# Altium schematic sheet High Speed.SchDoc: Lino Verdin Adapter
size A3; Organization: Toradex AG; Address1: Ebenaustrasse 10; Address2: Horw; Address3: 6048; Address4: Switzerland; DocumentNumber: 5; Revision: V1.1; SheetNumber: 5; SheetTotal: 8; PageSetup: Record=PageOptions¦CenterHorizontal=True¦CenterVertical=True¦PrintScale=0.73¦XCorrection=1.00¦YCorrection=1.00¦PrintKind=0¦BorderSize=5000000¦LeftOffset=0¦BottomOffset=0¦Orientation=2¦PaperLength=1000¦PaperWidth=1000¦Scale=100¦PaperSource=7¦PrintQuality=-4¦MediaType=1¦DitherType=10¦PaperKind=A4¦PrintScaleMode=1
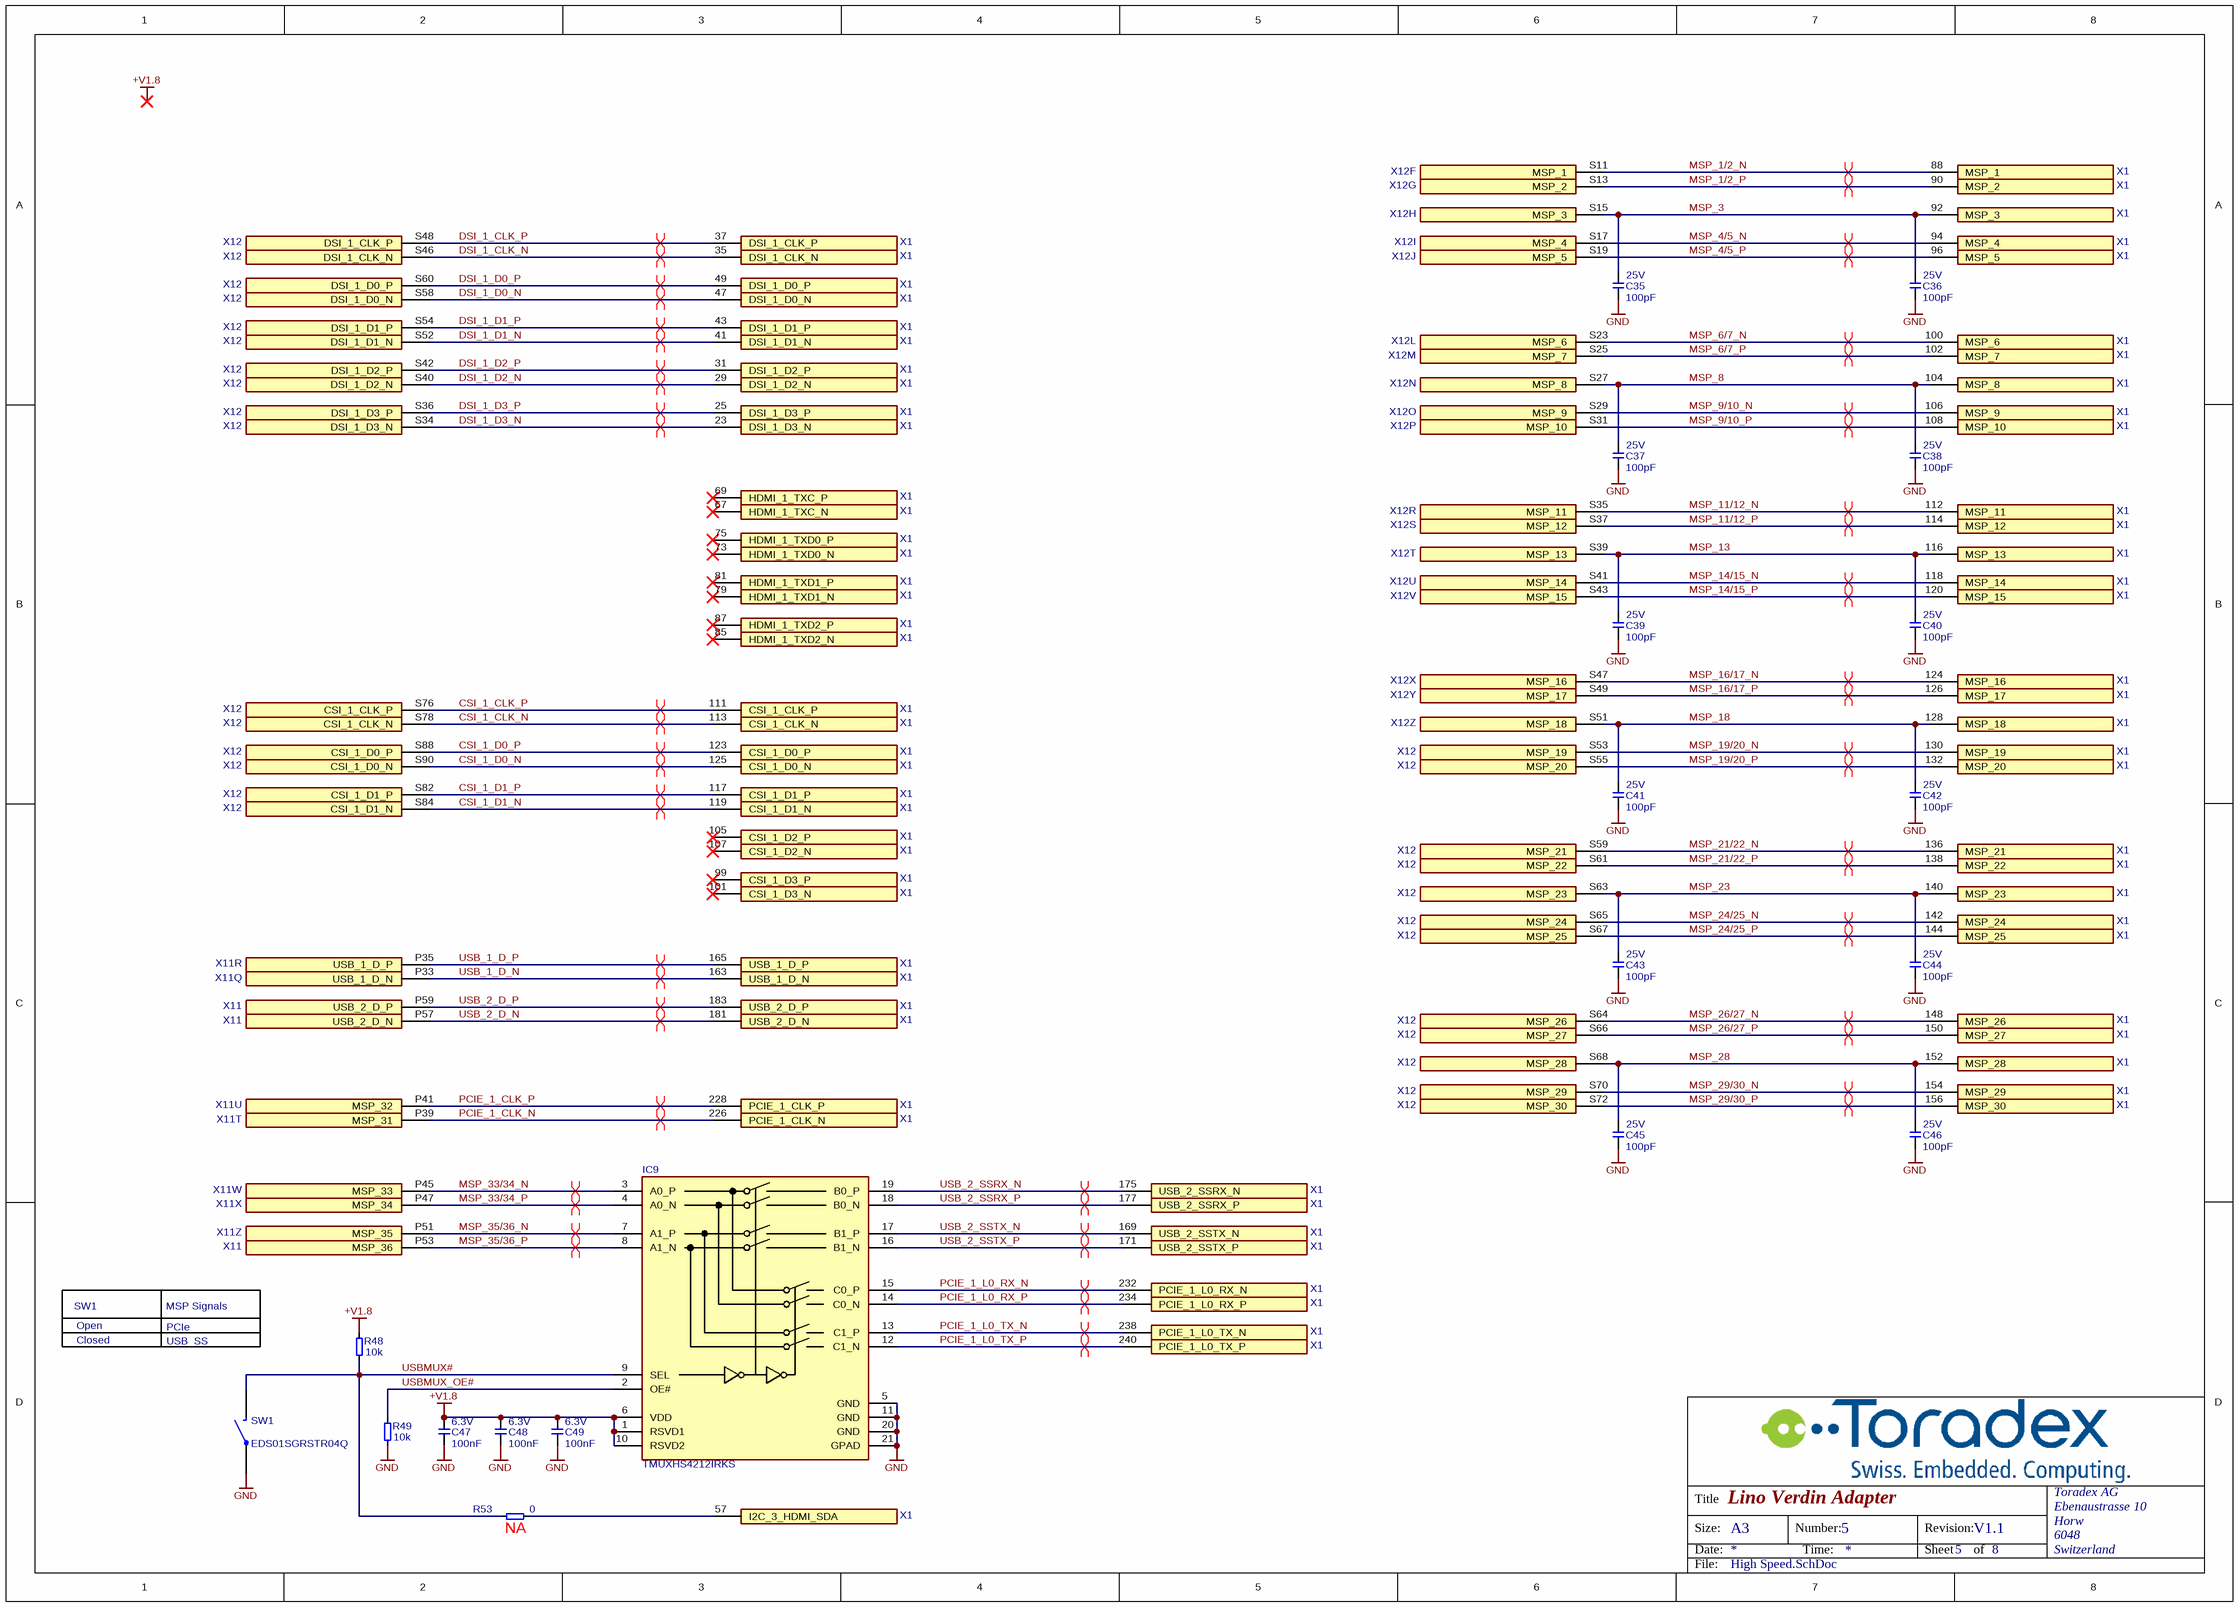
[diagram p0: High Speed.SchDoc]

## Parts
C35  value 100pF  Rating: 25V  [CAPC60X30X33L15L]  (hidden comment: C-NP0-100p-25V-5%-0201)
C36  value 100pF  Rating: 25V  [CAPC60X30X33L15L]  (hidden comment: C-NP0-100p-25V-5%-0201)
C37  value 100pF  Rating: 25V  [CAPC60X30X33L15L]  (hidden comment: C-NP0-100p-25V-5%-0201)
C38  value 100pF  Rating: 25V  [CAPC60X30X33L15L]  (hidden comment: C-NP0-100p-25V-5%-0201)
C39  value 100pF  Rating: 25V  [CAPC60X30X33L15L]  (hidden comment: C-NP0-100p-25V-5%-0201)
C40  value 100pF  Rating: 25V  [CAPC60X30X33L15L]  (hidden comment: C-NP0-100p-25V-5%-0201)
C41  value 100pF  Rating: 25V  [CAPC60X30X33L15L]  (hidden comment: C-NP0-100p-25V-5%-0201)
C42  value 100pF  Rating: 25V  [CAPC60X30X33L15L]  (hidden comment: C-NP0-100p-25V-5%-0201)
C43  value 100pF  Rating: 25V  [CAPC60X30X33L15L]  (hidden comment: C-NP0-100p-25V-5%-0201)
C44  value 100pF  Rating: 25V  [CAPC60X30X33L15L]  (hidden comment: C-NP0-100p-25V-5%-0201)
C45  value 100pF  Rating: 25V  [CAPC60X30X33L15L]  (hidden comment: C-NP0-100p-25V-5%-0201)
C46  value 100pF  Rating: 25V  [CAPC60X30X33L15L]  (hidden comment: C-NP0-100p-25V-5%-0201)
C47  value 100nF  Rating: 6.3V  [CAPC60X30X33L15L]  (hidden comment: C-X5R-100n-6.3V-10%-0201)
C48  value 100nF  Rating: 6.3V  [CAPC60X30X33L15L]  (hidden comment: C-X5R-100n-6.3V-10%-0201)
C49  value 100nF  Rating: 6.3V  [CAPC60X30X33L15L]  (hidden comment: C-X5R-100n-6.3V-10%-0201)
IC9  Manufacturer Part No.: TMUXHS4212IRKS  [QFN20P50-250X450X100L40X25T100X300L]  (hidden comment: IC-TI-TMUXHS4212IRKS)
R48  value 10k  [RESC60X30X33L15L]  (hidden comment: R-10K-50mW-1%-0201)
R49  value 10k  [RESC60X30X33L15L]  (hidden comment: R-10K-50mW-1%-0201)
R53  value 0  [RESC60X30X33L15L]  (hidden comment: R-0R-50mW-5%-0201)
SW1  Manufacturer Part No.: EDS01SGRSTR04Q  [CON-TE-Connectivity-EDS01SGRSTR04Q-6-2319848-4]  (hidden comment: CON-TE-Connectivity-EDS01SGRSTR04Q-6-2319848-4)
X1  CON-SODIMM-DDR4-TEST  [SODIMM_DDR4_no_Module]  (value not drawn)  (parts D,H,J,K,M,N,P,Q,37,38,40,41,43,44,46,47,49,50,53,58,59,61,62,64,65,67,68,74,75,77,78,79,80,82,83,85,86,105,107,108,110,111,113,114,193,194,195,196,197,199,200,201,202,203,205,206,207,208,210,211,212,213,214,216,217,218,219,220,222,223,224,225,226 of 260)  (no BOM)
X11  CON-LINO-P-CARRIER  [HIROSE_DF40C_100DS_LINO_CARRIER_PRIMARY]  (value not drawn)  (parts Q,R,T,U,W,X,Z,27,29,30 of 100)
X12  CON-LINO-S-CARRIER  [HIROSE_DF40C_100DS_LINO_CARRIER_SECONDARY]  (value not drawn)  (parts F,G,H,I,J,L,M,N,O,P,R,S,T,U,V,X,Y,Z,27,28,30,31,32,33,34,67,68,70,71,73,74,76,77,79,80,82,83,84,85,86,88,89,91,92,94,95 of 100)

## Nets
+V1.8: C47.2 C48.2 C49.2 IC9.1(RSVD1) IC9.6(VDD) IC9.10(RSVD2) R48.2
GND: C35.1 C36.1 C37.1 C38.1 C39.1 C40.1 C41.1 C42.1 C43.1 C44.1 C45.1 C46.1 C47.1 C48.1 C49.1 IC9.5(GND) IC9.11(GND) IC9.20(GND) IC9.21(GPAD) R49.1 SW1.2
CSI_1_CLK_N: X1.113(CSI_1_CLK_N) X12.S78(CSI_1_CLK_N)
CSI_1_CLK_P: X1.111(CSI_1_CLK_P) X12.S76(CSI_1_CLK_P)
CSI_1_D0_N: X1.125(CSI_1_D0_N) X12.S90(CSI_1_D0_N)
CSI_1_D0_P: X1.123(CSI_1_D0_P) X12.S88(CSI_1_D0_P)
CSI_1_D1_N: X1.119(CSI_1_D1_N) X12.S84(CSI_1_D1_N)
CSI_1_D1_P: X1.117(CSI_1_D1_P) X12.S82(CSI_1_D1_P)
DSI_1_CLK_N: X1.35(DSI_1_CLK_N) X12.S46(DSI_1_CLK_N)
DSI_1_CLK_P: X1.37(DSI_1_CLK_P) X12.S48(DSI_1_CLK_P)
DSI_1_D0_N: X1.47(DSI_1_D0_N) X12.S58(DSI_1_D0_N)
DSI_1_D0_P: X1.49(DSI_1_D0_P) X12.S60(DSI_1_D0_P)
DSI_1_D1_N: X1.41(DSI_1_D1_N) X12.S52(DSI_1_D1_N)
DSI_1_D1_P: X1.43(DSI_1_D1_P) X12.S54(DSI_1_D1_P)
DSI_1_D2_N: X1.29(DSI_1_D2_N) X12.S40(DSI_1_D2_N)
DSI_1_D2_P: X1.31(DSI_1_D2_P) X12.S42(DSI_1_D2_P)
DSI_1_D3_N: X1.23(DSI_1_D3_N) X12.S34(DSI_1_D3_N)
DSI_1_D3_P: X1.25(DSI_1_D3_P) X12.S36(DSI_1_D3_P)
MSP_1/2_N: X1.88(MSP_1) X12.S11(MSP_1)
MSP_1/2_P: X1.90(MSP_2) X12.S13(MSP_2)
MSP_3: C35.2 C36.2 X1.92(MSP_3) X12.S15(MSP_3)
MSP_4/5_N: X1.94(MSP_4) X12.S17(MSP_4)
MSP_4/5_P: X1.96(MSP_5) X12.S19(MSP_5)
MSP_6/7_N: X1.100(MSP_6) X12.S23(MSP_6)
MSP_6/7_P: X1.102(MSP_7) X12.S25(MSP_7)
MSP_8: C37.2 C38.2 X1.104(MSP_8) X12.S27(MSP_8)
MSP_9/10_N: X1.106(MSP_9) X12.S29(MSP_9)
MSP_9/10_P: X1.108(MSP_10) X12.S31(MSP_10)
MSP_11/12_N: X1.112(MSP_11) X12.S35(MSP_11)
MSP_11/12_P: X1.114(MSP_12) X12.S37(MSP_12)
MSP_13: C39.2 C40.2 X1.116(MSP_13) X12.S39(MSP_13)
MSP_14/15_N: X1.118(MSP_14) X12.S41(MSP_14)
MSP_14/15_P: X1.120(MSP_15) X12.S43(MSP_15)
MSP_16/17_N: X1.124(MSP_16) X12.S47(MSP_16)
MSP_16/17_P: X1.126(MSP_17) X12.S49(MSP_17)
MSP_18: C41.2 C42.2 X1.128(MSP_18) X12.S51(MSP_18)
MSP_19/20_N: X1.130(MSP_19) X12.S53(MSP_19)
MSP_19/20_P: X1.132(MSP_20) X12.S55(MSP_20)
MSP_21/22_N: X1.136(MSP_21) X12.S59(MSP_21)
MSP_21/22_P: X1.138(MSP_22) X12.S61(MSP_22)
MSP_23: C43.2 C44.2 X1.140(MSP_23) X12.S63(MSP_23)
MSP_24/25_N: X1.142(MSP_24) X12.S65(MSP_24)
MSP_24/25_P: X1.144(MSP_25) X12.S67(MSP_25)
MSP_26/27_N: X1.148(MSP_26) X12.S64(MSP_26)
MSP_26/27_P: X1.150(MSP_27) X12.S66(MSP_27)
MSP_28: C45.2 C46.2 X1.152(MSP_28) X12.S68(MSP_28)
MSP_29/30_N: X1.154(MSP_29) X12.S70(MSP_29)
MSP_29/30_P: X1.156(MSP_30) X12.S72(MSP_30)
MSP_33/34_N: IC9.3(A0_P) X11.P45(MSP_33)
MSP_33/34_P: IC9.4(A0_N) X11.P47(MSP_34)
MSP_35/36_N: IC9.7(A1_P) X11.P51(MSP_35)
MSP_35/36_P: IC9.8(A1_N) X11.P53(MSP_36)
PCIE_1_CLK_N: X1.226(PCIE_1_CLK_N) X11.P39(MSP_31)
PCIE_1_CLK_P: X1.228(PCIE_1_CLK_P) X11.P41(MSP_32)
PCIE_1_L0_RX_N: IC9.15(C0_P) X1.232(PCIE_1_L0_RX_N)
PCIE_1_L0_RX_P: IC9.14(C0_N) X1.234(PCIE_1_L0_RX_P)
PCIE_1_L0_TX_N: IC9.13(C1_P) X1.238(PCIE_1_L0_TX_N)
PCIE_1_L0_TX_P: IC9.12(C1_N) X1.240(PCIE_1_L0_TX_P)
USB_1_D_N: X1.163(USB_1_D_N) X11.P33(USB_1_D_N)
USB_1_D_P: X1.165(USB_1_D_P) X11.P35(USB_1_D_P)
USB_2_D_N: X1.181(USB_2_D_N) X11.P57(USB_2_D_N)
USB_2_D_P: X1.183(USB_2_D_P) X11.P59(USB_2_D_P)
USB_2_SSRX_N: IC9.19(B0_P) X1.175(USB_2_SSRX_N)
USB_2_SSRX_P: IC9.18(B0_N) X1.177(USB_2_SSRX_P)
USB_2_SSTX_N: IC9.17(B1_P) X1.169(USB_2_SSTX_N)
USB_2_SSTX_P: IC9.16(B1_N) X1.171(USB_2_SSTX_P)
USBMUX#: IC9.9(SEL) R48.1 R53.2 SW1.1
USBMUX_OE#: IC9.2(OE#) R49.2
NetR53_1: R53.1 X1.57(I2C_3_HDMI_SDA)

Not connected (* = marked no-connect by the designer): X1 67(HDMI_1_TXC_N)* 69(HDMI_1_TXC_P)* 73(HDMI_1_TXD0_N)* 75(HDMI_1_TXD0_P)* 79(HDMI_1_TXD1_N)* 81(HDMI_1_TXD1_P)* 85(HDMI_1_TXD2_N)* 87(HDMI_1_TXD2_P)* 99(CSI_1_D3_P)* 101(CSI_1_D3_N)* 105(CSI_1_D2_P)* 107(CSI_1_D2_N)*

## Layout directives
differential pair: CSI_1_CLK_N, CSI_1_CLK_P, CSI_1_D0_N, CSI_1_D0_P, CSI_1_D1_N, CSI_1_D1_P, DSI_1_CLK_N, DSI_1_CLK_P, DSI_1_D0_N, DSI_1_D0_P, DSI_1_D1_N, DSI_1_D1_P, DSI_1_D2_N, DSI_1_D2_P, DSI_1_D3_N, DSI_1_D3_P, MSP_1/2_N, MSP_1/2_P, MSP_4/5_N, MSP_4/5_P, MSP_6/7_N, MSP_6/7_P, MSP_9/10_N, MSP_9/10_P, MSP_11/12_N, MSP_11/12_P, MSP_14/15_N, MSP_14/15_P, MSP_16/17_N, MSP_16/17_P, MSP_19/20_N, MSP_19/20_P, MSP_21/22_N, MSP_21/22_P, MSP_24/25_N, MSP_24/25_P, MSP_26/27_N, MSP_26/27_P, MSP_29/30_N, MSP_29/30_P, USB_1_D_N, USB_1_D_P, USB_2_D_N, USB_2_D_P
differential pair; differential pair class USB: MSP_33/34_N, MSP_33/34_P, MSP_35/36_N, MSP_35/36_P, PCIE_1_CLK_N, PCIE_1_CLK_P, PCIE_1_L0_RX_N, PCIE_1_L0_RX_P, PCIE_1_L0_TX_N, PCIE_1_L0_TX_P, USB_2_SSRX_N, USB_2_SSRX_P, USB_2_SSTX_N, USB_2_SSTX_P

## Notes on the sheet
- SW1
- Open
- Closed
- MSP Signals
- PCIe
- USB_SS
- (near R53) NA
- Labels drawn without touching a wire or pin: +V1.8

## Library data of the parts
C35-C46 = CMP-00463-10: Capacitor Ceramic NP0 100pF 25V 5% 0201; Manufacturer Name: Generic
C47-C49 = CMP-00475-11: Capacitor Ceramic X5R 100nF 6.3V 20% 0201; Manufacturer Name: Generic; Tolerance: 10%
IC9 = CMP-00398-8: Differential Multiplexer, 2 Channel, 20-VQFN; Manufacturer Name: Texas Instruments
R48 R49 = CMP-00426-16: Resistor 10K ohm 50mW 1% 0201; Manufacturer Name: Generic
R53 = CMP-00402-19: Resistor 0 ohm 50mW 5% 0201; Manufacturer Name: Generic
SW1 = CMP-00979-2: DIP Switch SPST 1x Surface Mount; Max Voltage Rating (DC): 24V; Rating: 25mA
X1 = CMP-00731-8: DDR4 SODIMM Card Edge, 260 pins, 0.5mm Pitch; Manufacturer Name: Generic; Manufacturer Part No.: No Physical Component; Gender: Male
X11 = CMP-00961-5: LINO Primary Connector Carrier; Manufacturer Name: Amphenol; Manufacturer Part No.: 10164227-1001A1RLF; Rows: 2
X12 = CMP-00962-5: LINO Secondary Connector; Manufacturer Part No.: 10164227-1001A1RLF; Manufacturer Name: Amphenol; Rows: 2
